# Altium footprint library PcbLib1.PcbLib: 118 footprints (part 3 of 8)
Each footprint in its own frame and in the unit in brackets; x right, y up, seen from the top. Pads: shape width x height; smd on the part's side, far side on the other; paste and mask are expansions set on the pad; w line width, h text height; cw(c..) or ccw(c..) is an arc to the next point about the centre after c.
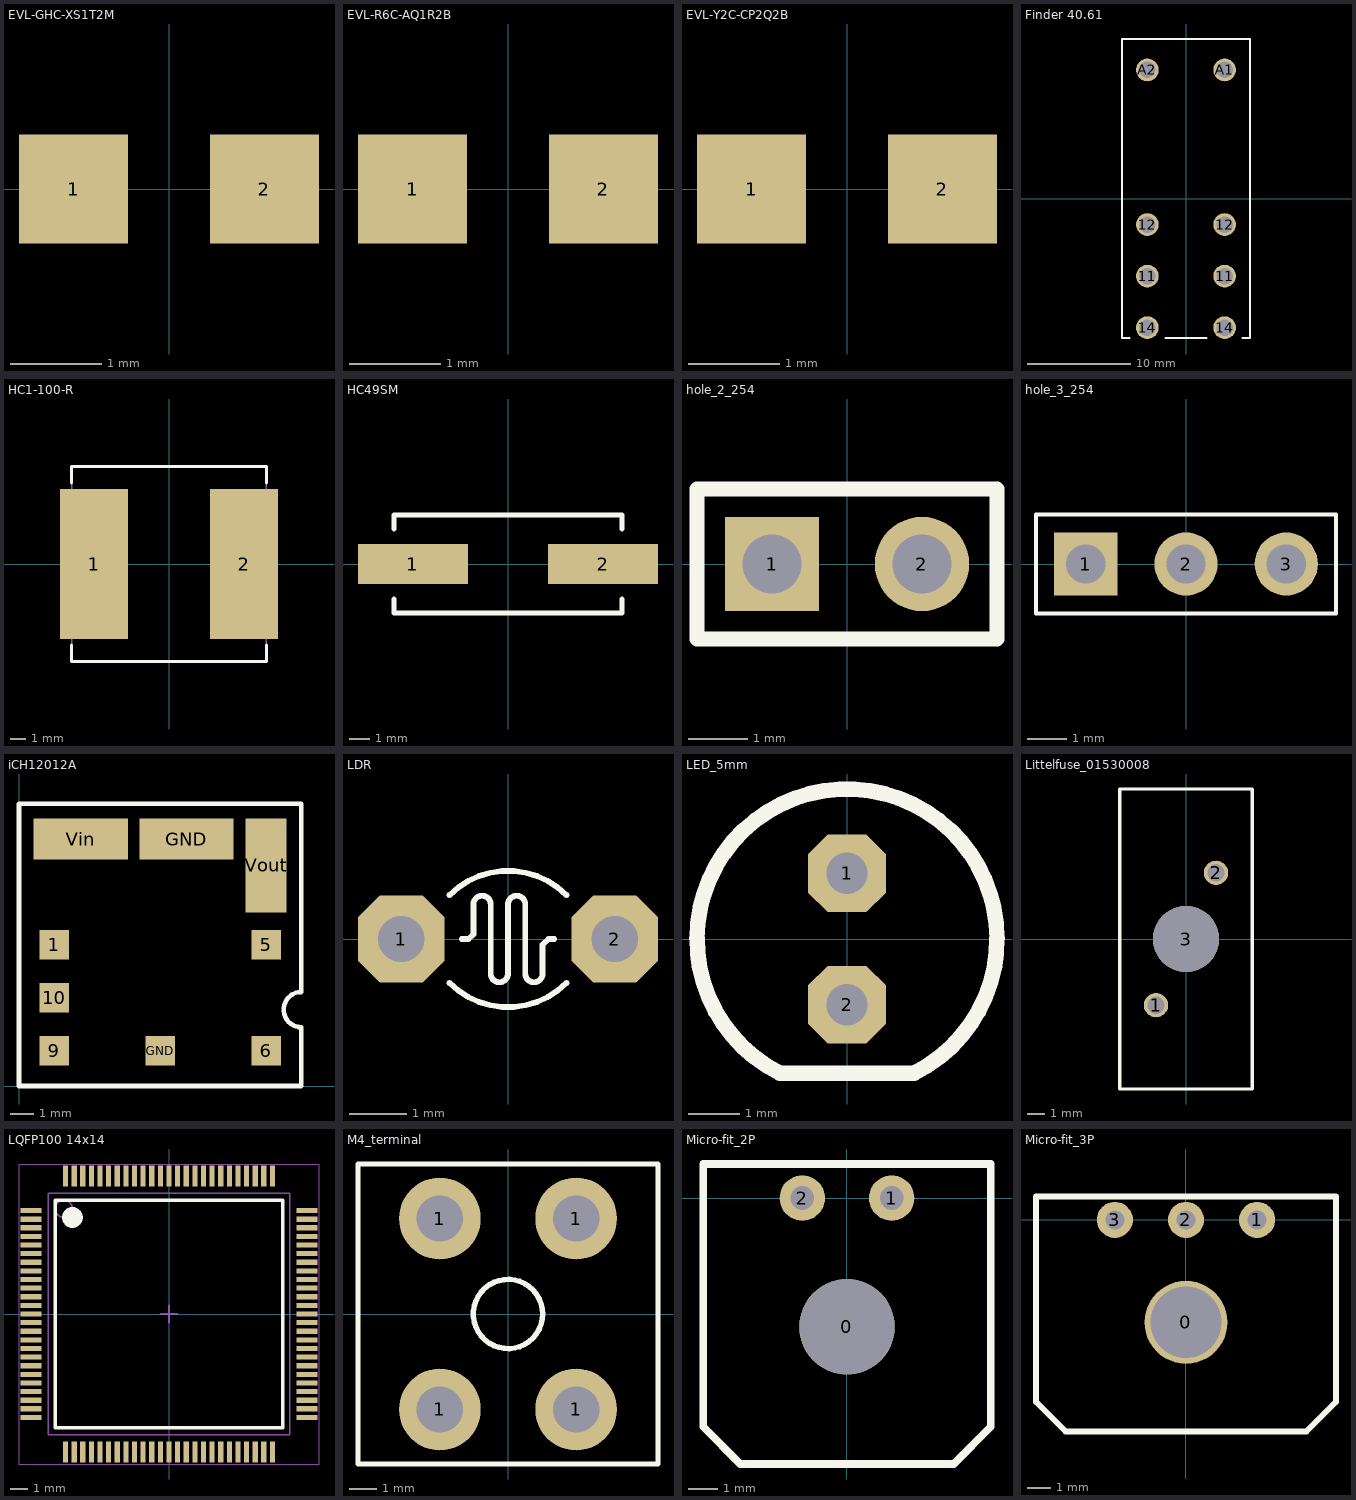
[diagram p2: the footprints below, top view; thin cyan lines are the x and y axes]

## EVL-GHC-XS1T2M [mm] "0805_Green"
pads (2):
  rect 1.2x1.2 smd: 1(-1.05,0) 2(1.05,0)
3D body "EVL-GHC-XS1T2M.STEP": height 1.1, standoff 0, extent -1,-0.625 1,0.625

## EVL-R6C-AQ1R2B [mm] "0805_Red"
pads (2):
  rect 1.2x1.2 smd: 1(-1.05,0) 2(1.05,0)
3D body "EVL-R6C-AQ1R2B.STEP": height 1.1, standoff 0, extent -1,-0.625 1,0.625

## EVL-Y2C-CP2Q2B [mm] "0805_Yellow"
pads (2):
  rect 1.2x1.2 smd: 1(-1.05,0) 2(1.05,0)
3D body "EVL-Y2C-CP2Q2B.STEP": height 1.1, standoff 0, extent -1,-0.625 1,0.625

## Finder 40.61 [mm] "40.61.7.012.2020 SPDT 16A"
pads (8):
  round 2.2 hole 1.6 unplated: 11(-3.75,-7.5) 11(3.75,-7.5) 12(-3.75,-2.5) 12(3.75,-2.5) 14(-3.75,-12.5) 14(3.75,-12.5) A1(3.75,12.5) A2(-3.75,12.5)
Top Overlay:
  lines w0.2: -5.5,-13.5 -6.2,-13.5 -6.2,15.5 6.2,15.5 6.2,-13.5 5.5,-13.5 ; -2,-13.5 2,-13.5
3D body "4061.stp": height 25.17, standoff -5.13, extent -6.2,-13.5 6.2,15.5

## HC1-100-R [mm] "Precision Wire Wound Inductor, 2-Leads, Body 13,00x13,00mm, IPC Medium Density"
height 10
pads (2):
  rect 4.5x10 smd: 1(-5,0) 2(5,0)
Top Overlay:
  lines w0.2: -6.5,-5.4 -6.5,-6.5 6.5,-6.5 6.5,-5.4 ; -6.5,5.4 -6.5,6.5 6.5,6.5 6.5,5.4
Mechanical 13:
  lines w0.1: -6.5,-6.5 6.5,-6.5 6.5,6.5 -6.5,6.5 -6.5,-6.5
3D body "HC1-100-R.step": height 10.1, standoff 0, extent -6.6,-6.5 6.6,6.5

## HC49SM [mm]
pads (2):
  rect 5.5x2 smd: 1(-4.75,0) 2(4.75,0)
Top Overlay:
  lines w0.254: -5.7,-1.75 -5.7,-2.45 5.7,-2.45 5.7,-1.75 ; -5.7,1.75 -5.7,2.45 5.7,2.45 5.7,1.75
3D body "HC49S.step": height 4.35, standoff 0, extent -6.15,-2.35 6.15,2.35

## hole_2_254 [mm]
pads (2):
  rect 1.6x1.6 hole 1: 1(-1.27,0)
  round 1.6 hole 1: 2(1.27,0)
Top Overlay:
  lines w0.254: -2.54,-1.27 2.54,-1.27 2.54,1.27 -2.54,1.27 -2.54,-1.27

## hole_3_254 [mm]
pads (3):
  rect 1.6x1.6 hole 1: 1(-2.54,0)
  round 1.6 hole 1: 2(0,0) 3(2.54,0)
Top Overlay:
  lines w0.1: -3.8,-1.25 -3.8,1.25 3.8,1.25 3.8,-1.25 -3.8,-1.25

## iCH12012A [mil] "iCH12012A007V-007-R"
pads (9):
  rect 50x50 smd: 1(60,240) 5(420,240) 6(420,60) 9(60,60) 10(60,150) GND(240,60)
  rect 160x70 smd: GND(285,420) Vin(105,420)
  rect 70x160 smd: Vout(420,375)
Top Overlay:
  lines w7.87: 0,0 480,0 480,100 cw(c480,130) 480,160 480,480 0,480 0,0
3D body "ich_asm.STEP": height 328.5, standoff -0.93, extent 0,0 480,480

## LDR [mm] "pitch 3.7mm"
pads (2):
  oct 1.5x1.5 hole 0.8: 1(-1.85,0) 2(1.85,0)
Top Overlay:
  lines w0.1: -1.016,-0.762 ccw(c0,0.254) 1.016,-0.762 ; -1.016,0.762 cw(c0,-0.254) 1.016,0.762 ; -0.8,0 -0.684,0 -0.6,0.084 -0.6,0.6 cw(c-0.45,0.6) -0.3,0.6 -0.3,-0.6 ccw(c-0.15,-0.6) 0,-0.6 0,0.6 cw(c0.15,0.6) 0.3,0.6 0.3,-0.6 ccw(c0.45,-0.6) 0.6,-0.6 0.6,-0.1 0.7,0 0.8,0

## LED_5mm [mm] "std 5mm LED"
pads (2):
  oct 1.5x1.5 hole 0.8: 1(0,1.27) 2(0,-1.27)
Top Overlay:
  lines w0.3: -1.3,-2.6 1.3,-2.6 ; -1.297,-2.594 cw(c0,0) 1.297,-2.594
3D body "LED5mm.STEP": height 8.7, standoff -1.7, extent -2.898,-2.6 2.898,2.9

## Littelfuse_01530008 [mm] "Fuse holder w fuse"
pads (3):
  round 1.4 hole 1: 1(-1.727,-3.81) 2(1.727,3.81)
  round 3.81 hole 3.81 unplated paste+0: 3(0,0)
Top Overlay:
  lines w0.2: -3.81,-8.636 3.81,-8.636 3.81,8.636 -3.81,8.636 -3.81,-8.636
3D body "Littelfuse_0153008asm.stp": height 19.18, standoff -3.84, extent -3.841,-8.65 3.759,8.65

## LQFP100 14x14 [mm] "LQFP, 100-Leads, Body 14,00x14,00mm, Pitch 0,50mm, IPC Medium Density"
height 1.6
pads (100):
  rect 1.2x0.3 smd: 1(-8,6) 2(-8,5.5) 3(-8,5) 4(-8,4.5) 5(-8,4) 6(-8,3.5) 7(-8,3) 8(-8,2.5) 9(-8,2) 10(-8,1.5) 11(-8,1) 12(-8,0.5) 13(-8,0) 14(-8,-0.5) 15(-8,-1) 16(-8,-1.5) 17(-8,-2) 18(-8,-2.5) 19(-8,-3) 20(-8,-3.5) 21(-8,-4) 22(-8,-4.5) 23(-8,-5) 24(-8,-5.5) 25(-8,-6) 51(8,-6) 52(8,-5.5) 53(8,-5) 54(8,-4.5) 55(8,-4) 56(8,-3.5) 57(8,-3) 58(8,-2.5) 59(8,-2) 60(8,-1.5) 61(8,-1) 62(8,-0.5) 63(8,0) 64(8,0.5) 65(8,1) 66(8,1.5) 67(8,2) 68(8,2.5) 69(8,3) 70(8,3.5) 71(8,4) 72(8,4.5) 73(8,5) 74(8,5.5) 75(8,6)
  rect 0.3x1.2 smd: 26(-6,-8) 27(-5.5,-8) 28(-5,-8) 29(-4.5,-8) 30(-4,-8) 31(-3.5,-8) 32(-3,-8) 33(-2.5,-8) 34(-2,-8) 35(-1.5,-8) 36(-1,-8) 37(-0.5,-8) 38(0,-8) 39(0.5,-8) 40(1,-8) 41(1.5,-8) 42(2,-8) 43(2.5,-8) 44(3,-8) 45(3.5,-8) 46(4,-8) 47(4.5,-8) 48(5,-8) 49(5.5,-8) 50(6,-8) 76(6,8) 77(5.5,8) 78(5,8) 79(4.5,8) 80(4,8) 81(3.5,8) 82(3,8) 83(2.5,8) 84(2,8) 85(1.5,8) 86(1,8) 87(0.5,8) 88(0,8) 89(-0.5,8) 90(-1,8) 91(-1.5,8) 92(-2,8) 93(-2.5,8) 94(-3,8) 95(-3.5,8) 96(-4,8) 97(-4.5,8) 98(-5,8) 99(-5.5,8) 100(-6,8)
Top Overlay:
  circle w0.6: c-5.6,5.6 r0.3
  lines w0.2: -6.6,-6.6 -6.6,6.6 6.6,6.6 6.6,-6.6 -6.6,-6.6
Mechanical 13:
  circle w0.1: c-6.1,6.1 r0.5
  lines w0.1: -7,-7 -7,7 7,7 7,-7 -7,-7
Mechanical 15:
  lines w0.05: -8.7,-8.7 -8.7,8.7 8.7,8.7 8.7,-8.7 -8.7,-8.7
  lines w0.1: -0.5,0 0.5,0 ; 0,-0.5 0,0.5
3D body "LWFP100 14x14.step": height 1.6, standoff 0, extent -8,-8 8,8

## M4_terminal [mm] "PCB-66"
pads (4):
  round 3 hole 1.7: 1(-2.5,-3.5) 1(-2.5,3.5) 1(2.5,-3.5) 1(2.5,3.5)
Top Overlay:
  circle w0.2: c0,0 r1.27
  lines w0.2: -5.5,-5.5 5.5,-5.5 5.5,5.5 -5.5,5.5 -5.5,-5.5
3D body "keystone-PN7797.STEP": height 6.49, standoff -4.69, extent -3.937,-4.444 3.937,4.7

## Micro-fit_2P [mm] "horizontal"
pads (3):
  round 3.2 hole 3.2 unplated: 0(0,-4.32)
  round 1.524 hole 0.8: 1(1.5,0) 2(-1.5,0)
Top Overlay:
  lines w0.254: -4.825,-7.675 -4.825,1.143 4.825,1.143 4.825,-7.675 3.58,-8.92 -3.58,-8.92 -4.825,-7.675
3D body "436500200.stp": height 5.62, standoff -3.29, extent -4.825,-8.884 4.825,1.016

## Micro-fit_3P [mm] "horizontal"
pads (4):
  round 3.5 hole 3 unplated: 0(0,-4.32)
  round 1.524 hole 0.8: 1(3,0) 2(0,0) 3(-3,0)
Top Overlay:
  lines w0.254: -6.325,-7.675 -5.08,-8.92 5.08,-8.92 6.325,-7.675 6.325,0.98 -6.325,0.98 -6.325,-7.675
3D body "436500300.stp": height 5.62, standoff -3.29, extent -6.325,-8.884 6.325,1.016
